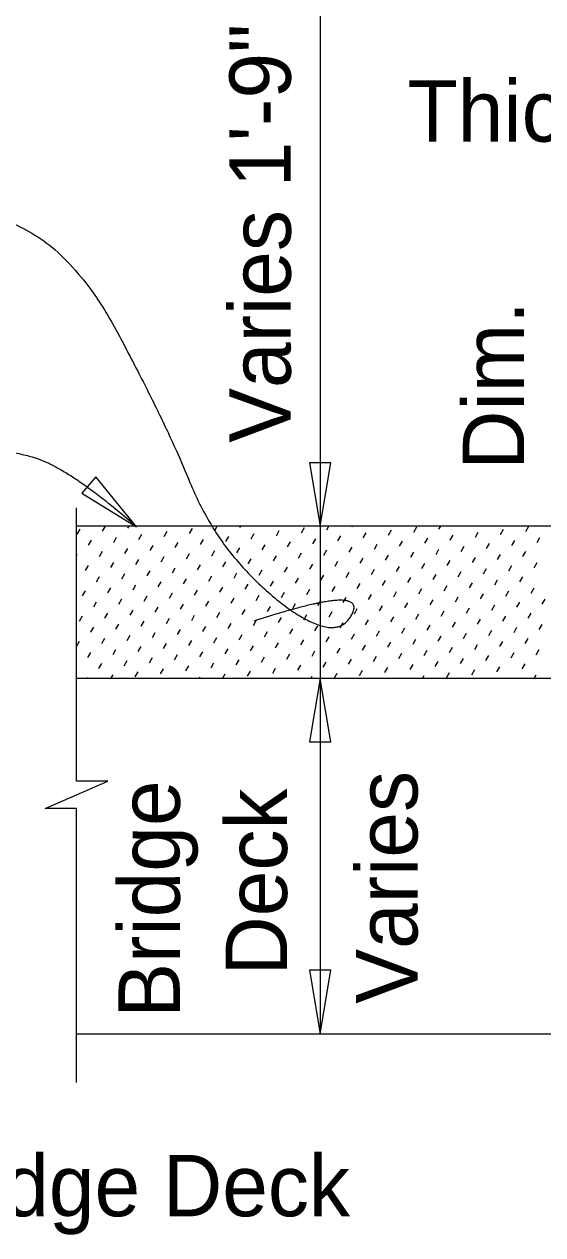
# Model space of a CAD drawing. Extents: x 21516.9 to 21586.2, y 56154.7 to 56195.
# Drawn here: x 21520.857 to 21522.56, y 56180.737 to 56184.712 of the extents above; entities that cross this region are included whole.
import ezdxf

# ---------------------------------------------------------------- set-up
doc = ezdxf.new("R2010")
doc.units = 0
for name, color, linetype in [('AdhocPoint_dp', 7, 'Continuous'), ('Border', 7, 'Continuous'), ('PlotBorder_dp', 7, 'Continuous'), ('SheetBorder_dp', 7, 'Continuous')]:
    doc.layers.add(name, color=color, linetype=linetype)

msp = doc.modelspace()

# ---------------------------------------------------------------- linework, layer by layer
at = {"layer": 'AdhocPoint_dp'}
for p, q in [((21524.9618, 56182.5642), (21521.0284, 56182.5642)), ((21521.0284, 56181.3976), (21526.3371, 56181.3976))]:
    msp.add_line(p, q, dxfattribs=at)
at = {"layer": 'Border'}
for p, q in [((21525.0205, 56183.0642), (21521.0284, 56183.0642)), ((21521.0312, 56183.0378), (21521.0409, 56183.0546)), ((21521.1142, 56183.0475), (21521.1238, 56183.0642)), ((21521.1971, 56183.0572), (21521.2012, 56183.0642)), ((21521.2337, 56183.0206), (21521.2434, 56183.0374)), ((21521.3166, 56183.0303), (21521.3264, 56183.0471)), ((21521.3996, 56183.0401), (21521.4093, 56183.0569)), ((21521.4825, 56183.0498), (21521.4909, 56183.0642)), ((21521.5655, 56183.0595), (21521.5682, 56183.0642)), ((21521.6021, 56183.0229), (21521.6118, 56183.0397)), ((21521.685, 56183.0326), (21521.6947, 56183.0494)), ((21521.7679, 56183.0423), (21521.7777, 56183.0591)), ((21521.8509, 56183.0521), (21521.8579, 56183.0642)), ((21521.9338, 56183.0618), (21521.9352, 56183.0642)), ((21521.9704, 56183.0252), (21521.9801, 56183.042)), ((21522.0534, 56183.0349), (21522.0631, 56183.0517)), ((21522.1363, 56183.0446), (21522.146, 56183.0614)), ((21522.2192, 56183.0543), (21522.225, 56183.0642)), ((21522.3022, 56183.0641), (21522.3023, 56183.0642)), ((21522.3388, 56183.0275), (21522.3485, 56183.0443)), ((21522.4217, 56183.0372), (21522.4314, 56183.054)), ((21522.5047, 56183.0469), (21522.5144, 56183.0637)), ((21521.0678, 56183.0012), (21521.0775, 56183.018)), ((21521.1508, 56183.0109), (21521.1605, 56183.0277)), ((21521.2703, 56182.984), (21521.28, 56183.0008)), ((21521.3532, 56182.9937), (21521.363, 56183.0105)), ((21521.4362, 56183.0034), (21521.4459, 56183.0202)), ((21521.5191, 56183.0132), (21521.5288, 56183.03)), ((21521.6387, 56182.9863), (21521.6484, 56183.0031)), ((21521.7216, 56182.996), (21521.7313, 56183.0128)), ((21521.8045, 56183.0057), (21521.8143, 56183.0225)), ((21521.8875, 56183.0155), (21521.8972, 56183.0322)), ((21522.007, 56182.9886), (21522.0167, 56183.0054)), ((21522.09, 56182.9983), (21522.0997, 56183.0151)), ((21522.1729, 56183.008), (21522.1826, 56183.0248)), ((21522.2558, 56183.0177), (21522.2656, 56183.0345)), ((21522.2924, 56182.9811), (21522.3022, 56182.9979)), ((21522.3754, 56182.9909), (21522.3851, 56183.0076)), ((21522.4583, 56183.0006), (21522.468, 56183.0174)), ((21522.5413, 56183.0103), (21522.551, 56183.0271)), ((21521.0284, 56182.9668), (21521.0312, 56182.9716)), ((21521.1044, 56182.9646), (21521.1142, 56182.9814)), ((21521.1874, 56182.9743), (21521.1971, 56182.9911)), ((21521.3069, 56182.9474), (21521.3166, 56182.9642)), ((21521.3899, 56182.9571), (21521.3996, 56182.9739)), ((21521.4728, 56182.9668), (21521.4825, 56182.9836)), ((21521.5557, 56182.9766), (21521.5655, 56182.9934)), ((21521.5923, 56182.94), (21521.6021, 56182.9568)), ((21521.6753, 56182.9497), (21521.685, 56182.9665)), ((21521.7582, 56182.9594), (21521.7679, 56182.9762)), ((21521.8412, 56182.9691), (21521.8509, 56182.9859)), ((21521.9241, 56182.9788), (21521.9338, 56182.9956)), ((21521.9607, 56182.9422), (21521.9704, 56182.959)), ((21522.0436, 56182.952), (21522.0534, 56182.9688)), ((21522.1266, 56182.9617), (21522.1363, 56182.9785)), ((21522.2095, 56182.9714), (21522.2192, 56182.9882)), ((21522.3291, 56182.9445), (21522.3388, 56182.9613)), ((21522.412, 56182.9542), (21522.4217, 56182.971)), ((21522.4949, 56182.964), (21522.5047, 56182.9808)), ((21521.0581, 56182.9182), (21521.0678, 56182.935)), ((21521.141, 56182.928), (21521.1508, 56182.9447)), ((21521.224, 56182.9377), (21521.2337, 56182.9545)), ((21521.2606, 56182.9011), (21521.2703, 56182.9179)), ((21521.3435, 56182.9108), (21521.3532, 56182.9276)), ((21521.4265, 56182.9205), (21521.4362, 56182.9373)), ((21521.5094, 56182.9302), (21521.5191, 56182.947)), ((21521.6289, 56182.9033), (21521.6387, 56182.9201)), ((21521.7119, 56182.9131), (21521.7216, 56182.9299)), ((21521.7948, 56182.9228), (21521.8045, 56182.9396)), ((21521.8778, 56182.9325), (21521.8875, 56182.9493)), ((21521.9973, 56182.9056), (21522.007, 56182.9224)), ((21522.0802, 56182.9154), (21522.09, 56182.9321)), ((21522.1632, 56182.9251), (21522.1729, 56182.9419)), ((21522.2461, 56182.9348), (21522.2558, 56182.9516)), ((21522.3657, 56182.9079), (21522.3754, 56182.9247)), ((21522.4486, 56182.9176), (21522.4583, 56182.9344)), ((21522.5315, 56182.9274), (21522.5413, 56182.9442)), ((21521.0947, 56182.8816), (21521.1044, 56182.8984)), ((21521.1776, 56182.8913), (21521.1874, 56182.9081)), ((21521.2972, 56182.8645), (21521.3069, 56182.8813)), ((21521.3801, 56182.8742), (21521.3899, 56182.891)), ((21521.4631, 56182.8839), (21521.4728, 56182.9007)), ((21521.546, 56182.8936), (21521.5557, 56182.9104)), ((21521.6656, 56182.8667), (21521.6753, 56182.8835)), ((21521.7485, 56182.8765), (21521.7582, 56182.8933)), ((21521.8314, 56182.8862), (21521.8412, 56182.903)), ((21521.9144, 56182.8959), (21521.9241, 56182.9127)), ((21522.0339, 56182.869), (21522.0436, 56182.8858)), ((21522.1168, 56182.8787), (21522.1266, 56182.8955)), ((21522.1998, 56182.8885), (21522.2095, 56182.9053)), ((21522.2827, 56182.8982), (21522.2924, 56182.915)), ((21522.3193, 56182.8616), (21522.3291, 56182.8784)), ((21522.4023, 56182.8713), (21522.412, 56182.8881)), ((21522.4852, 56182.881), (21522.4949, 56182.8978)), ((21521.0484, 56182.8353), (21521.0581, 56182.8521)), ((21521.1313, 56182.845), (21521.141, 56182.8618)), ((21521.2143, 56182.8547), (21521.224, 56182.8715)), ((21521.3338, 56182.8279), (21521.3435, 56182.8446)), ((21521.4167, 56182.8376), (21521.4265, 56182.8544)), ((21521.4997, 56182.8473), (21521.5094, 56182.8641)), ((21521.5826, 56182.857), (21521.5923, 56182.8738)), ((21521.7022, 56182.8301), (21521.7119, 56182.8469)), ((21521.7851, 56182.8399), (21521.7948, 56182.8567)), ((21521.868, 56182.8496), (21521.8778, 56182.8664)), ((21521.951, 56182.8593), (21521.9607, 56182.8761)), ((21521.9876, 56182.8227), (21521.9973, 56182.8395)), ((21522.0705, 56182.8324), (21522.0802, 56182.8492)), ((21522.1535, 56182.8421), (21522.1632, 56182.8589)), ((21522.2364, 56182.8519), (21522.2461, 56182.8687)), ((21522.3559, 56182.825), (21522.3657, 56182.8418)), ((21522.4389, 56182.8347), (21522.4486, 56182.8515)), ((21522.5218, 56182.8444), (21522.5315, 56182.8612)), ((21521.085, 56182.7987), (21521.0947, 56182.8155)), ((21521.1679, 56182.8084), (21521.1776, 56182.8252)), ((21521.2509, 56182.8181), (21521.2606, 56182.8349)), ((21521.2875, 56182.7815), (21521.2972, 56182.7983)), ((21521.3704, 56182.7912), (21521.3801, 56182.808)), ((21521.4533, 56182.801), (21521.4631, 56182.8178)), ((21521.5363, 56182.8107), (21521.546, 56182.8275)), ((21521.6192, 56182.8204), (21521.6289, 56182.8372)), ((21521.6558, 56182.7838), (21521.6656, 56182.8006)), ((21521.7388, 56182.7935), (21521.7485, 56182.8103)), ((21521.8217, 56182.8033), (21521.8314, 56182.82)), ((21521.9046, 56182.813), (21521.9144, 56182.8298)), ((21522.0242, 56182.7861), (21522.0339, 56182.8029)), ((21522.1071, 56182.7958), (21522.1168, 56182.8126)), ((21522.1901, 56182.8055), (21522.1998, 56182.8223)), ((21522.273, 56182.8153), (21522.2827, 56182.8321)), ((21522.3925, 56182.7884), (21522.4023, 56182.8052)), ((21522.4755, 56182.7981), (21522.4852, 56182.8149)), ((21522.5584, 56182.8078), (21522.5681, 56182.8246)), ((21521.0387, 56182.7524), (21521.0484, 56182.7691)), ((21521.1216, 56182.7621), (21521.1313, 56182.7789)), ((21521.2045, 56182.7718), (21521.2143, 56182.7886)), ((21521.3241, 56182.7449), (21521.3338, 56182.7617)), ((21521.407, 56182.7546), (21521.4167, 56182.7714)), ((21521.49, 56182.7644), (21521.4997, 56182.7812)), ((21521.5729, 56182.7741), (21521.5826, 56182.7909)), ((21521.6924, 56182.7472), (21521.7022, 56182.764)), ((21521.7754, 56182.7569), (21521.7851, 56182.7737)), ((21521.8583, 56182.7666), (21521.868, 56182.7834)), ((21521.9413, 56182.7764), (21521.951, 56182.7932)), ((21522.0608, 56182.7495), (21522.0705, 56182.7663)), ((21522.1437, 56182.7592), (21522.1535, 56182.776)), ((21522.2267, 56182.7689), (21522.2364, 56182.7857)), ((21522.3096, 56182.7786), (21522.3193, 56182.7954)), ((21522.3462, 56182.742), (21522.3559, 56182.7588)), ((21522.4292, 56182.7518), (21522.4389, 56182.7686)), ((21522.5121, 56182.7615), (21522.5218, 56182.7783)), ((21521.0753, 56182.7157), (21521.085, 56182.7325)), ((21521.1582, 56182.7255), (21521.1679, 56182.7423)), ((21521.2411, 56182.7352), (21521.2509, 56182.752)), ((21521.3607, 56182.7083), (21521.3704, 56182.7251)), ((21521.4436, 56182.718), (21521.4533, 56182.7348)), ((21521.5266, 56182.7278), (21521.5363, 56182.7445)), ((21521.6095, 56182.7375), (21521.6192, 56182.7543)), ((21521.729, 56182.7106), (21521.7388, 56182.7274)), ((21521.812, 56182.7203), (21521.8217, 56182.7371)), ((21521.8949, 56182.73), (21521.9046, 56182.7468)), ((21521.9779, 56182.7398), (21521.9876, 56182.7566)), ((21522.0145, 56182.7032), (21522.0242, 56182.7199)), ((21522.0974, 56182.7129), (21522.1071, 56182.7297)), ((21522.1803, 56182.7226), (21522.1901, 56182.7394)), ((21522.2633, 56182.7323), (21522.273, 56182.7491)), ((21522.3828, 56182.7054), (21522.3925, 56182.7222)), ((21522.4658, 56182.7152), (21522.4755, 56182.732)), ((21522.5487, 56182.7249), (21522.5584, 56182.7417)), ((21521.0289, 56182.6694), (21521.0387, 56182.6862)), ((21521.1119, 56182.6791), (21521.1216, 56182.6959)), ((21521.1948, 56182.6889), (21521.2045, 56182.7057)), ((21521.2777, 56182.6986), (21521.2875, 56182.7154)), ((21521.3144, 56182.662), (21521.3241, 56182.6788)), ((21521.3973, 56182.6717), (21521.407, 56182.6885)), ((21521.4802, 56182.6814), (21521.49, 56182.6982)), ((21521.5632, 56182.6911), (21521.5729, 56182.7079)), ((21521.6461, 56182.7009), (21521.6558, 56182.7177)), ((21521.6827, 56182.6643), (21521.6924, 56182.6811)), ((21521.7657, 56182.674), (21521.7754, 56182.6908)), ((21521.8486, 56182.6837), (21521.8583, 56182.7005)), ((21521.9315, 56182.6934), (21521.9413, 56182.7102)), ((21522.0511, 56182.6665), (21522.0608, 56182.6833)), ((21522.134, 56182.6763), (21522.1437, 56182.6931)), ((21522.2169, 56182.686), (21522.2267, 56182.7028)), ((21522.2999, 56182.6957), (21522.3096, 56182.7125)), ((21522.4194, 56182.6688), (21522.4292, 56182.6856)), ((21522.5024, 56182.6785), (21522.5121, 56182.6953)), ((21521.0655, 56182.6328), (21521.0753, 56182.6496)), ((21521.1485, 56182.6425), (21521.1582, 56182.6593)), ((21521.2314, 56182.6523), (21521.2411, 56182.669)), ((21521.351, 56182.6254), (21521.3607, 56182.6422)), ((21521.4339, 56182.6351), (21521.4436, 56182.6519)), ((21521.5168, 56182.6448), (21521.5266, 56182.6616)), ((21521.5998, 56182.6545), (21521.6095, 56182.6713)), ((21521.7193, 56182.6277), (21521.729, 56182.6444)), ((21521.8023, 56182.6374), (21521.812, 56182.6542)), ((21521.8852, 56182.6471), (21521.8949, 56182.6639)), ((21521.9681, 56182.6568), (21521.9779, 56182.6736)), ((21522.0877, 56182.6299), (21522.0974, 56182.6467)), ((21522.1706, 56182.6397), (21522.1803, 56182.6565)), ((21522.2536, 56182.6494), (21522.2633, 56182.6662)), ((21522.3365, 56182.6591), (21522.3462, 56182.6759)), ((21522.3731, 56182.6225), (21522.3828, 56182.6393)), ((21522.456, 56182.6322), (21522.4658, 56182.649)), ((21522.539, 56182.6419), (21522.5487, 56182.6587)), ((21521.0284, 56182.6024), (21521.0289, 56182.6033)), ((21521.1022, 56182.5962), (21521.1119, 56182.613)), ((21521.1851, 56182.6059), (21521.1948, 56182.6227)), ((21521.268, 56182.6156), (21521.2777, 56182.6324)), ((21521.3876, 56182.5888), (21521.3973, 56182.6056)), ((21521.4705, 56182.5985), (21521.4802, 56182.6153)), ((21521.5534, 56182.6082), (21521.5632, 56182.625)), ((21521.6364, 56182.6179), (21521.6461, 56182.6347)), ((21521.7559, 56182.591), (21521.7657, 56182.6078)), ((21521.8389, 56182.6008), (21521.8486, 56182.6176)), ((21521.9218, 56182.6105), (21521.9315, 56182.6273)), ((21522.0047, 56182.6202), (21522.0145, 56182.637)), ((21522.0414, 56182.5836), (21522.0511, 56182.6004)), ((21522.1243, 56182.5933), (21522.134, 56182.6101)), ((21522.2072, 56182.6031), (21522.2169, 56182.6198)), ((21522.2902, 56182.6128), (21522.2999, 56182.6296)), ((21522.4097, 56182.5859), (21522.4194, 56182.6027)), ((21522.4926, 56182.5956), (21522.5024, 56182.6124)), ((21521.0641, 56182.5642), (21521.0655, 56182.5667)), ((21521.1414, 56182.5642), (21521.1485, 56182.5764)), ((21521.2217, 56182.5693), (21521.2314, 56182.5861)), ((21521.3046, 56182.579), (21521.3144, 56182.5958)), ((21521.4312, 56182.5642), (21521.4339, 56182.5689)), ((21521.5085, 56182.5642), (21521.5168, 56182.5787)), ((21521.5901, 56182.5716), (21521.5998, 56182.5884)), ((21521.673, 56182.5813), (21521.6827, 56182.5981)), ((21521.7982, 56182.5642), (21521.8023, 56182.5712)), ((21521.8755, 56182.5642), (21521.8852, 56182.581)), ((21521.9584, 56182.5739), (21521.9681, 56182.5907)), ((21522.1652, 56182.5642), (21522.1706, 56182.5735)), ((21522.2438, 56182.5664), (21522.2536, 56182.5832)), ((21522.3268, 56182.5762), (21522.3365, 56182.593)), ((21522.455, 56182.5642), (21522.456, 56182.5661)), ((21522.5323, 56182.5642), (21522.539, 56182.5758))]:
    msp.add_line(p, q, dxfattribs=at)
at = {"layer": 'PlotBorder_dp'}
msp.add_line((21521.8287, 56188.3976), (21521.8287, 56181.3976), dxfattribs=at)
for points in [[(21521.8287, 56183.0642), (21521.864, 56183.2725), (21521.7934, 56183.2725)], [(21521.226, 56183.0623), (21521.0925, 56183.226), (21521.046, 56183.1729)], [(21521.8287, 56182.5642), (21521.7934, 56182.356), (21521.864, 56182.356)], [(21521.8287, 56181.3976), (21521.864, 56181.6058), (21521.7934, 56181.6058)]]:
    msp.add_lwpolyline(points, close=True, dxfattribs=at)
msp.add_lwpolyline([(21521.0285, 56181.2372), (21521.0285, 56182.1369), (21520.9252, 56182.1369), (21521.0285, 56182.1819), (21521.1319, 56182.2269), (21521.0285, 56182.2269), (21521.0285, 56183.1239)], dxfattribs=at)
for points in [[(21519.5352, 56184.2121), (21519.9555, 56184.2121), (21520.6028, 56184.1348), (21521.0086, 56183.9899), (21521.3226, 56183.4005), (21521.4675, 56183.043), (21521.6946, 56182.8015), (21521.8878, 56182.7049), (21521.9651, 56182.8208), (21521.825, 56182.8208), (21521.6125, 56182.7532)], [(21519.9651, 56183.3908), (21520.226, 56183.3908), (21520.4965, 56183.3908), (21520.7526, 56183.3232), (21520.9941, 56183.2652), (21521.226, 56183.0623)]]:
    msp.add_open_spline(points, degree=2, dxfattribs=at)

# ---------------------------------------------------------------- texts
msp.add_text('Thick Neoprene Pad', height=0.2016, dxfattribs=at).set_placement((21522.1163, 56184.3264))
for s, p in [('Bridge', (21521.3681, 56181.4502)), ('Deck', (21521.7201, 56181.5885))]:
    msp.add_text(s, height=0.2016, rotation=90, dxfattribs=at).set_placement(p)
at = {"layer": 'SheetBorder_dp'}
for s, p in [('Varies 1\'-9" to 2\'-0"', (21521.7324, 56183.3377)), ('Dim.', (21522.499, 56183.249)), ('Varies', (21522.1488, 56181.4961))]:
    msp.add_text(s, height=0.2016, rotation=90, dxfattribs=at).set_placement(p)
msp.add_text('Existing Bridge Deck', height=0.2016, dxfattribs=at).set_placement((21519.4397, 56180.7982))

doc.saveas('drawing.dxf')
